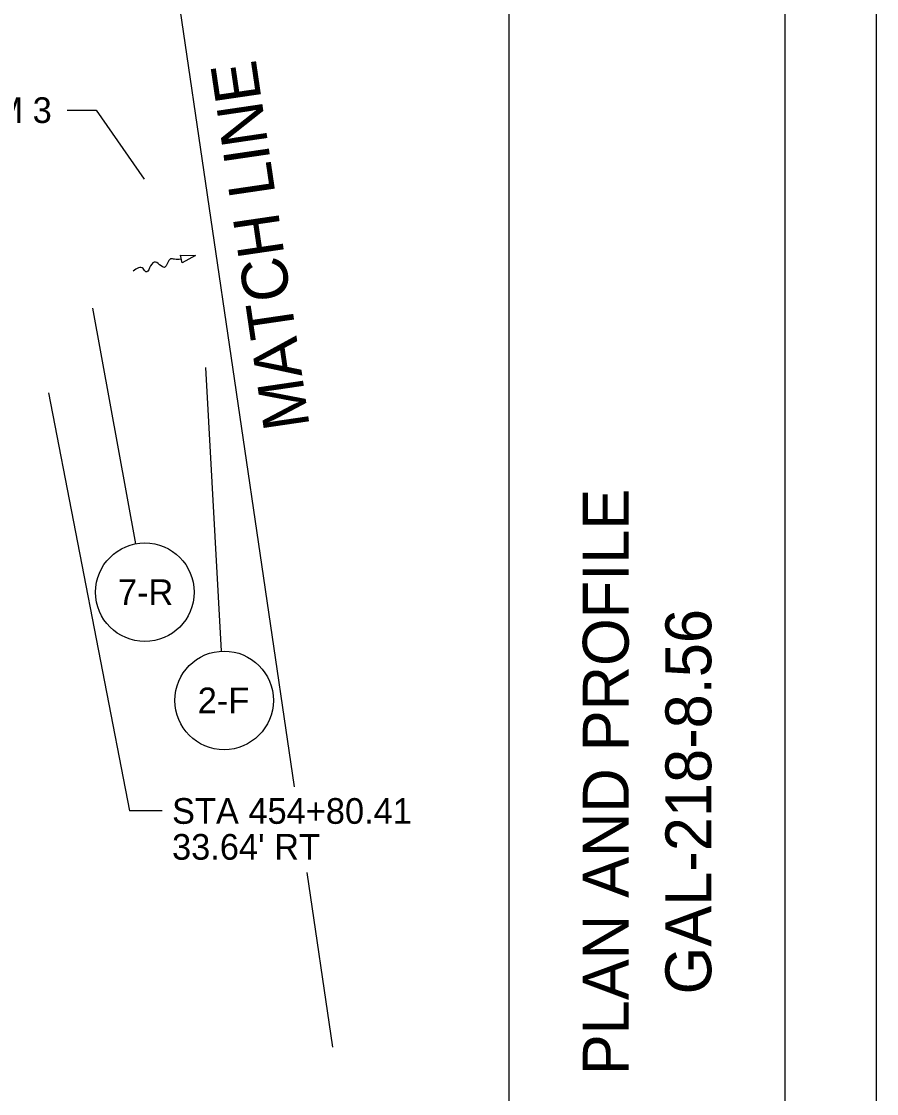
# Model space of a CAD drawing. Extents: x 0 to 3369, y -440 to 440.
# Drawn here: x 586.9 to 680, y 202.5 to 319.4 of the extents above; entities that cross this region are included whole.
import ezdxf

# ---------------------------------------------------------------- set-up
doc = ezdxf.new("R2010")
doc.units = 0
for name, color, linetype in [('DR_X_Culvert', 7, 'Continuous'), ('PF_X_Ground_Line', 7, 'Continuous'), ('PV_P_EOP', 7, 'Continuous'), ('PV_P_Shoulder', 7, 'Continuous'), ('SC_Scratch1', 7, 'Continuous')]:
    doc.layers.add(name, color=color, linetype=linetype)

msp = doc.modelspace()

# ---------------------------------------------------------------- linework, layer by layer
at = {"layer": 'PF_X_Ground_Line'}
msp.add_line((640, 10), (640, 430), dxfattribs=at)
msp.add_lwpolyline([(30, 430), (670, 430), (670, 10), (30, 10)], close=True, dxfattribs=at)
at = {"layer": 'PV_P_EOP'}
for p, q in [((616.61, 235.96), (588.72, 425.67)), ((591.84, 309.71), (594.99, 309.71)), ((594.99, 309.71), (600.22, 302.19)), ((599.33, 262.46), (594.62, 288.13)), ((608.64, 250.76), (606.94, 281.67)), ((589.8, 278.91), (598.63, 233.34)), ((602.2, 233.34), (598.63, 233.34)), ((620.78, 207.61), (617.99, 226.62))]:
    msp.add_line(p, q, dxfattribs=at)
for centre in [(600.3, 257.18), (608.93, 245.39)]:
    msp.add_circle(centre, 5.37, dxfattribs=at)
at = {"layer": 'PV_P_Shoulder'}
for p, q in [((604.17, 293.9), (605.83, 293.87)), ((604.38, 293.07), (604.17, 293.9)), ((605.83, 293.87), (604.38, 293.07))]:
    msp.add_line(p, q, dxfattribs=at)
msp.add_spline([(604.28, 293.49), (604.21, 293.47), (603.54, 293.46), (603.1, 293.5), (602.45, 292.58), (601.31, 293.15), (600.42, 292.08), (600.1, 292.46), (599.03, 292.18)], degree=3, dxfattribs=at)
at = {"layer": 'SC_Scratch1'}
msp.add_lwpolyline([(0, 0), (680, 0), (680, 440), (0, 440)], close=True, dxfattribs=at)

# ---------------------------------------------------------------- texts
at = {"layer": 'DR_X_Culvert'}
for s, rotation, p in [('MATCH LINE    STA 455+00', 98.3657, (618.26, 275.26)), ('PLAN AND PROFILE', 90, (653, 204.55)), ('GAL-218-8.56', 90, (662, 213.35))]:
    msp.add_text(s, height=5, rotation=rotation, dxfattribs=at).set_placement(p)
at = {"layer": 'PV_P_EOP'}
for s, p in [('BM 3', (581.42, 308.31)), ('7-R', (597.36, 255.78)), ('2-F', (606.06, 243.99)), ('STA 454+80.41', (603.26, 231.94)), ("33.64' RT", (603.26, 228.03))]:
    msp.add_text(s, height=2.8, dxfattribs=at).set_placement(p)

doc.saveas('drawing.dxf')
